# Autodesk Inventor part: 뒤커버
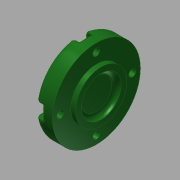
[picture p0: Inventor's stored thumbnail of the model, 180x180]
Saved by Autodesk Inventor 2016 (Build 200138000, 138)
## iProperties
Created: 2015-11
Part Number: 뒤커버
Material: 알루미늄 6061
Document SubType Name: Modeling
Designer: mduedu
Density: 1 g/cm^3
Appearance: 매끄러움 - 짙은 산림 녹색
Author: mduedu
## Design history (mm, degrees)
sketch "스케치1"
  geometry: L1 (-7, 0)-(7, 0); L2 (-7, 0)-(-7, 27.5); L3 (-7, 27.5)-(4, 27.5); L4 (4, 27.5)-(4, 16); L5 (4, 16)-(7, 16); L6 (7, 16)-(7, 0); 2 further points
  constraints: 12 end point, 3 perpendicular, 2 parallel, 1 coincident, 1 horizontal, 1 midpoint
  dimensions: "d0" = 14 distance of L1.start L1.end; "d1" = 55 diameter of L3 L1; "d2" = 3 distance of L4.end L5.end; "d3" = 32 diameter of L5 L1
revolve "회전1" sketch "스케치1" stored, may be unused: angle "d4" = 90 deg
hole "구멍1" diameter "d7" = 25; stored, may be unused: countersink angle "d11" = 90 deg, drill point angle "d13" = 0 deg; dims "d5" = 10, "d6" = 10, "d8" = 6, "d9" = 4, "d10" = 2, "d12" = 3
fillet "모깎기2" dims "d36" = 3
fillet "모깎기3" dims "d37" = 3
sketch "스케치2" dims "d39" = 45
  geometry: C1 r 12.846 at (0, 0) reference; C2 r 24.5 at (0, 0) reference; 6 further points
  constraints: 2 vertical alignment, 1 coincident, 7 other
  dimensions: "d42" = 360 deg dimension on point (0, 0) point (0, 22.5) (derived)
sketch "스케치3"
  geometry: 8 further points
  constraints: 4 coincident
hole "구멍4" sketch "스케치3" at (-22.5, 0), (0, -22.5), (22.5, 0), (0, 22.5) diameter "d44" = 4.5; stored, may be unused: countersink angle "d48" = 90 deg, drill point angle "d50" = 0 deg; dims "d45" = 6, "d46" = 8, "d47" = 4.6, "d49" = 8
sketch "스케치4"
  geometry: L1 (-4, 0)-(-4, -4.708); L2 (4, 0)-(4, -4.708); A1 r 4 centre (0, 0) between (-4, 0) and (4, 0) reference; A2 r 27.5 centre (0, 22.5) between (-4, -4.708) and (4, -4.708) reference; 3 further points
  constraints: 4 end point, 4 point on circle, 2 tangent, 1 parallel, 1 vertical
extrude "돌출1" cut sketch "스케치4" stored distance "d51" = 0; taper "d52" = 0 deg
fillet "모깎기5" dims "d56" = 0.3
fillet "모깎기6" dims "d57" = 1
node "솔리드1"
pattern_circular "원형 패턴1" dims angle "d54" = 360 deg
